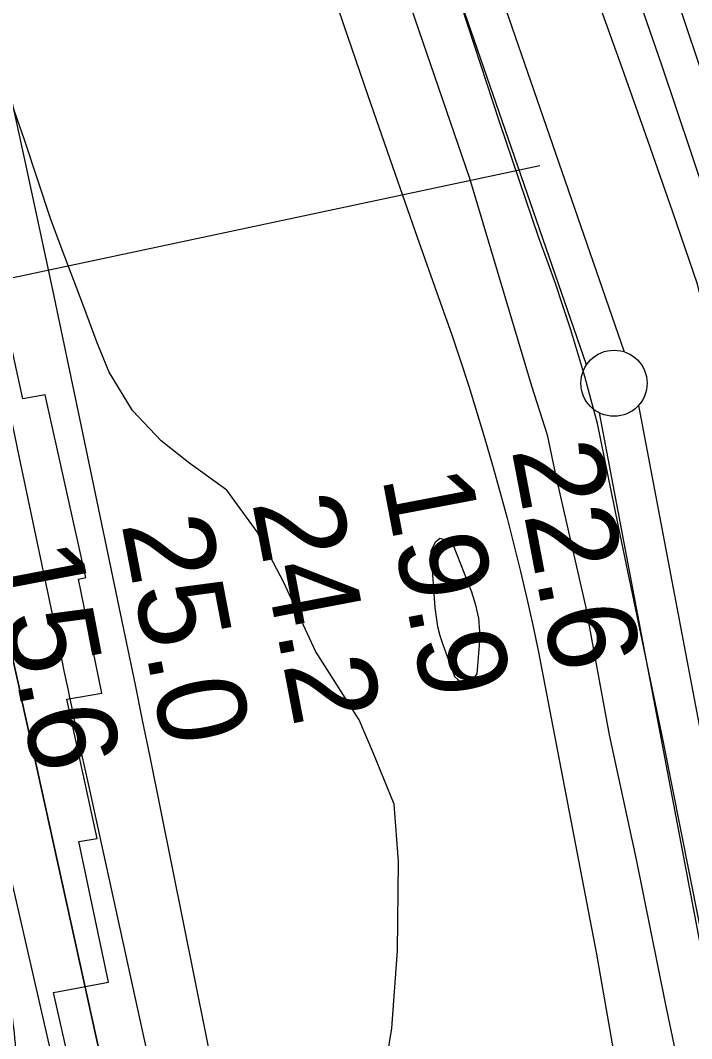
# Model space of a CAD drawing. Extents: x 3419139 to 3457078, y 540382 to 565875.
# Drawn here: x 3438392 to 3438899, y 560354 to 561123 of the extents above; entities that cross this region are included whole.
import ezdxf

# ---------------------------------------------------------------- set-up
doc = ezdxf.new("R2010")
doc.units = 0
for name, color, linetype in [('V-FLOD-BASE', 7, 'Continuous'), ('V-LEVE-TOET', 7, 'Continuous'), ('V-RIVR-EDGE', 7, 'Continuous'), ('V-RIVR-RANG', 7, 'Continuous'), ('V-ROAD-CNTR', 7, 'Continuous'), ('V-RRAP-RVMT', 7, 'Continuous'), ('V-SITE-VEGE', 7, 'Continuous'), ('V-SURV-LINE', 7, 'Continuous'), ('V-TOPO-DPTH', 7, 'Continuous'), ('V-TOPO-MINR', 7, 'Continuous'), ('V-TOPO-SHOR', 7, 'Continuous')]:
    doc.layers.add(name, color=color, linetype=linetype)

msp = doc.modelspace()

# ---------------------------------------------------------------- linework, layer by layer
at = {"layer": 'V-FLOD-BASE'}
msp.add_lwpolyline([(3438936.83, 560256.01), (3438910.24, 560411.52), (3438877.32, 560577.59), (3438843.24, 560742.06), (3438827.54, 560818.46), (3438822.83, 560836.28), (3438817.88, 560854.03), (3438812.7, 560871.71), (3438807.27, 560889.33), (3438801.62, 560906.87), (3438795.73, 560924.33), (3438789.61, 560941.72), (3438783.25, 560959.02), (3438768.28, 561002.74), (3438753.54, 561046.54), (3438739.06, 561090.43), (3438724.81, 561134.39), (3438681.33, 561259.64), (3438638.09, 561385.11), (3438603.78, 561479.91)], dxfattribs=at)
at = {"layer": 'V-LEVE-TOET'}
for points in [[(3439036.17, 560284.58), (3439005.58, 560458.4), (3438966.61, 560642.32), (3438926.07, 560829.68), (3438903.17, 560923.95), (3438884.4, 560978.26), (3438865.44, 561032.5), (3438846.3, 561086.68), (3438826.96, 561140.78), (3438803.44, 561211.66), (3438779.72, 561282.46), (3438755.81, 561353.2), (3438731.71, 561423.88), (3438707.41, 561494.49), (3438682.93, 561565.04), (3438594.19, 561820.57), (3438586.24, 561840.71), (3438578.51, 561860.93), (3438571, 561881.24), (3438563.71, 561901.62), (3438556.63, 561922.09), (3438549.78, 561942.62)], [(3438551.04, 561517.73), (3438603.27, 561370.49), (3438645.62, 561247.77), (3438686.65, 561132.59), (3438730.79, 561004.14), (3438777.7, 560847.12), (3438789.56, 560810.04), (3438796.42, 560777.55), (3438818.39, 560680.55), (3438836.23, 560583.12), (3438856.62, 560489.09), (3438878.73, 560380.44), (3438897.99, 560288.02)]]:
    msp.add_lwpolyline(points, dxfattribs=at)
at = {"layer": 'V-RIVR-EDGE'}
msp.add_spline([(3438546.81, 559762.45), (3438546.48, 559773.37), (3438550.38, 559782.17), (3438553.94, 559794.85), (3438553.95, 559801.19), (3438550.09, 559808.25), (3438545.88, 559813.9), (3438539.19, 559814.97), (3438534.96, 559814.98), (3438529.32, 559817.11), (3438525.81, 559821.7), (3438525.12, 559826.28), (3438524.78, 559831.57), (3438523.38, 559837.56), (3438520.59, 559848.84), (3438511.11, 559860.14), (3438495.63, 559870.75), (3438485.43, 559880.29), (3438480.87, 559888.41), (3438480.88, 559891.23), (3438481.95, 559896.16), (3438481.25, 559899.33), (3438477.03, 559903.22), (3438475.63, 559906.75), (3438475.65, 559913.44), (3438475.67, 559921.19), (3438473.57, 559926.48), (3438467.26, 559942), (3438464.1, 559944.83), (3438463.41, 559950.12), (3438461.31, 559956.82), (3438459.2, 559959.64), (3438456.04, 559962.12), (3438452.16, 559963.18), (3438448.99, 559963.19), (3438445.47, 559962.85), (3438445.12, 559964.96), (3438440.92, 559978.01), (3438437.77, 559985.07), (3438436.02, 559990.71), (3438435.34, 559998.46), (3438433.24, 560005.87), (3438430.44, 560014.68), (3438423.78, 560027.39), (3438420.62, 560033.74), (3438416.41, 560039.03), (3438415.01, 560042.21), (3438413.96, 560045.03), (3438413.99, 560059.83), (3438414.35, 560061.24), (3438414.01, 560066.17), (3438409.82, 560080.28), (3438408.77, 560083.45), (3438408.78, 560089.79), (3438407.38, 560092.62), (3438404.22, 560098.97), (3438402.12, 560103.2), (3438401.08, 560110.95), (3438400.42, 560127.87), (3438402.92, 560139.85), (3438403.67, 560158.52), (3438405.1, 560166.97), (3438407.93, 560174.72), (3438411.83, 560181.76), (3438413.61, 560188.45), (3438413.98, 560198.66), (3438415.78, 560211.35), (3438415.11, 560225.79), (3438409.53, 560248.71), (3438396.95, 560292.79), (3438389.99, 560329.81), (3438386.55, 560361.88), (3438383.09, 560386.91), (3438377.88, 560420.05), (3438373.01, 560444.02), (3438370.61, 560472.57), (3438371.75, 560503.93), (3438375.68, 560525.06), (3438378.52, 560533.16), (3438382.06, 560543.01), (3438382.09, 560551.82), (3438379.3, 560565.22), (3438376.85, 560570.51), (3438372.27, 560572.64), (3438366.99, 560574.06), (3438362.77, 560575.83), (3438362.77, 560577.59), (3438365.6, 560580.76), (3438366.66, 560585.34), (3438364.21, 560589.57), (3438360.34, 560594.51), (3438354.03, 560606.86), (3438350.54, 560618.5), (3438349.84, 560621.67), (3438346.68, 560624.85), (3438344.58, 560632.61), (3438342.85, 560643.54), (3438342.88, 560655.87)], degree=3, dxfattribs=at)
at = {"layer": 'V-RIVR-RANG'}
msp.add_line((3438784.02, 561013.45), (3437629.88, 560767.78), dxfattribs=at)
at = {"layer": 'V-ROAD-CNTR'}
msp.add_lwpolyline([(3438236.79, 562981.24), (3438373.02, 562618.8), (3438459.71, 562364.56), (3438556, 562079.12), (3438666.52, 561772.01), (3438772.05, 561478.7), (3438851.32, 561247.16), (3438925.31, 561027.3)], dxfattribs=at)
at = {"layer": 'V-RRAP-RVMT'}
for p, q in [((3438393.44, 560837.25), (3438366.44, 560959.87)), ((3438410.32, 560840.12), (3438393.44, 560837.25)), ((3438441.07, 560702.12), (3438410.32, 560840.12)), ((3438435.56, 560700.79), (3438441.07, 560702.12)), ((3438453.17, 560614.73), (3438435.56, 560700.79)), ((3438426.76, 560610.1), (3438453.17, 560614.73)), ((3438449.51, 560504.88), (3438426.76, 560610.1)), ((3438435.7, 560502.72), (3438449.51, 560504.88)), ((3438458.08, 560396.29), (3438435.7, 560502.72)), ((3438416.49, 560388.45), (3438458.08, 560396.29)), ((3438436.78, 560299.04), (3438416.49, 560388.45))]:
    msp.add_line(p, q, dxfattribs=at)
at = {"layer": 'V-SITE-VEGE'}
for points in [[(3438599.47, 561227.65), (3438617.44, 561173.86), (3438635.6, 561120.13), (3438653.97, 561066.48), (3438672.54, 561012.89), (3438691.31, 560959.37), (3438710.28, 560905.92), (3438717.13, 560886.29), (3438723.77, 560866.58), (3438730.2, 560846.81), (3438736.43, 560826.96), (3438742.44, 560807.06), (3438748.25, 560787.09), (3438753.84, 560767.06), (3438759.22, 560746.97), (3438764.39, 560726.83), (3438769.34, 560706.64), (3438774.08, 560686.39), (3438778.61, 560666.1), (3438782.92, 560645.75), (3438826.85, 560417.46), (3438854.7, 560257.47)], [(3438672.28, 560361.51), (3438676.43, 560419.88), (3438677.3, 560487.55), (3438673.96, 560530.93), (3438658.38, 560569.1), (3438647.5, 560594.56), (3438614.57, 560646.59), (3438590.41, 560699), (3438570.45, 560736.74), (3438547.48, 560768.2), (3438518.53, 560789.02), (3438497.8, 560805.35), (3438476.19, 560828.51), (3438458.54, 560857.46), (3438449.57, 560879.49), (3438438.75, 560908.84), (3438423.21, 560949.94), (3438414.25, 560973.43), (3438394.57, 561033.08), (3438378.13, 561080.52), (3438366.45, 561118.64), (3438358.21, 561160.14)], [(3438663.83, 560310.49), (3438672.28, 560361.51)]]:
    msp.add_lwpolyline(points, dxfattribs=at)
at = {"layer": 'V-SURV-LINE'}
for points in [[(3438212.34, 562711.39), (3438847.65, 560872.78)], [(3438819.29, 560862.99), (3438183.98, 562701.6)], [(3438858.45, 560832.18), (3439023.87, 559960)], [(3438994.39, 559954.4), (3438828.98, 560826.58)]]:
    msp.add_lwpolyline(points, dxfattribs=at)
msp.add_circle((3438839.99, 560849), 25, dxfattribs=at)
at = {"layer": 'V-TOPO-DPTH'}
msp.add_lwpolyline([(3438004.71, 562255.88), (3438076.09, 561993.59), (3438102.81, 561893.14), (3438128.75, 561792.49), (3438153.53, 561691.55), (3438177.53, 561590.41), (3438212.12, 561440.84), (3438218.2, 561414.33), (3438224.21, 561387.81), (3438230.13, 561361.27), (3438235.98, 561334.72), (3438258.24, 561232.78), (3438275.13, 561155.24), (3438291.97, 561077.69), (3438308.73, 561000.12), (3438325.44, 560922.53), (3438386.98, 560636.02), (3438390.38, 560620.29), (3438393.78, 560604.56), (3438397.21, 560588.83), (3438400.66, 560573.1), (3438516.42, 560047.04)], dxfattribs=at)
at = {"layer": 'V-TOPO-MINR'}
for points in [[(3438516.42, 560047.04), (3438400.66, 560573.1), (3438397.21, 560588.83), (3438393.78, 560604.56), (3438390.38, 560620.29), (3438386.98, 560636.02), (3438325.44, 560922.53), (3438308.73, 561000.12), (3438291.97, 561077.69), (3438275.13, 561155.24), (3438258.24, 561232.78), (3438235.98, 561334.72), (3438230.13, 561361.27), (3438224.21, 561387.81), (3438218.2, 561414.33), (3438212.12, 561440.84), (3438177.53, 561590.41), (3438153.53, 561691.55), (3438128.75, 561792.49), (3438102.81, 561893.14), (3438076.09, 561993.59), (3438004.71, 562255.88)], [(3438420.07, 560319.59), (3438372.07, 560528.81), (3438364.27, 560563.07), (3438356.55, 560597.35), (3438348.93, 560631.65), (3438341.4, 560665.97), (3438334.24, 560698.81), (3438323.16, 560749.56), (3438312.05, 560800.3), (3438300.89, 560851.04), (3438289.71, 560901.76), (3438186.97, 561366.68), (3438185.53, 561373.17), (3438184.08, 561379.65), (3438182.63, 561386.14), (3438181.16, 561392.62), (3438033.42, 562043), (3438023.97, 562083.45)], [(3438574.18, 560145.77), (3438489.24, 560567.85), (3438483.87, 560594.41), (3438478.46, 560620.96), (3438473, 560647.5), (3438467.49, 560674.03), (3438436.55, 560822.46), (3438416.02, 560919.72), (3438395.18, 561016.91), (3438373.87, 561114), (3438352.25, 561211.03), (3438317.39, 561365.68), (3438312.92, 561385.32), (3438308.39, 561404.94), (3438303.78, 561424.54), (3438299.11, 561444.13), (3438208.21, 561821.53), (3438188.08, 561904.04), (3438167.63, 561986.47), (3438146.69, 562068.77)], [(3438594.08, 559855.68), (3438443.44, 560543.93), (3438440.99, 560555.16), (3438438.56, 560566.4), (3438436.13, 560577.64), (3438433.73, 560588.88), (3438431.79, 560597.93), (3438430.36, 560604.65), (3438428.94, 560611.37), (3438427.54, 560618.09), (3438426.14, 560624.82), (3438424.74, 560631.54), (3438423.34, 560638.27), (3438421.94, 560644.99), (3438420.53, 560651.72), (3438390.66, 560794), (3438374.32, 560871.87), (3438358.01, 560949.74), (3438341.73, 561027.62), (3438325.47, 561105.5), (3438274.65, 561349.14)], [(3438708.53, 560731.67), (3438704.77, 560728.51), (3438701.68, 560722.43), (3438704.75, 560679.33), (3438705.55, 560672.22), (3438706.74, 560665.19), (3438708.51, 560658.29), (3438710.66, 560651.47), (3438719.43, 560627.22), (3438724.35, 560622.96), (3438728.91, 560621.46), (3438732.92, 560624.08), (3438736.58, 560629.47), (3438738.45, 560651), (3438738.62, 560661.23), (3438737.86, 560671.32), (3438735.71, 560681.21), (3438732.64, 560690.96), (3438718.71, 560726.29), (3438713.29, 560730.44), (3438708.53, 560731.67)]]:
    msp.add_lwpolyline(points, dxfattribs=at)
at = {"layer": 'V-TOPO-SHOR'}
msp.add_lwpolyline([(3439169.66, 559683.37), (3439129.31, 559913.87), (3439089.42, 560109.33), (3439043, 560357.74), (3439002.57, 560575.87), (3438944.76, 560866.28), (3438934.04, 560905.53), (3438909.86, 560988.85), (3438876.19, 561089.42), (3438815.53, 561265.08), (3438731.95, 561504.12), (3438640.92, 561760.4), (3438597.09, 561883.03), (3438577.54, 561939.51)], dxfattribs=at)

# ---------------------------------------------------------------- texts
at = {"layer": 'V-RIVR-RANG'}
for s, p in [('22.6', (3438762.52, 560798.86)), ('19.9', (3438664.64, 560778.28)), ('24.2', (3438566.52, 560759.01)), ('25.0', (3438467.8, 560742.84)), ('15.6', (3438369.82, 560722.78))]:
    msp.add_text(s, height=67, rotation=280.81833, dxfattribs=at).set_placement(p)

doc.saveas('drawing.dxf')
